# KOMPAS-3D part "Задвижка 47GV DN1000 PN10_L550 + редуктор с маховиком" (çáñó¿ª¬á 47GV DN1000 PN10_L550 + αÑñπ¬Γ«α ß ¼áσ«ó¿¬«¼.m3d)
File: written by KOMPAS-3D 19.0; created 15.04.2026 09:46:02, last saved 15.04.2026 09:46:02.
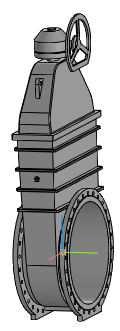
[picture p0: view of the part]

Document properties: Автор: Энергия; Полное имя файла: ..\..\Задвижка 47GV DN1000 PN10_L550 + редуктор с маховиком.a3d

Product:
- Part/product: Задвижка 47GV DN1000 PN10_L550 + редуктор с маховиком
    Масса: 5122.91

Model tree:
1. Операция без истории:1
